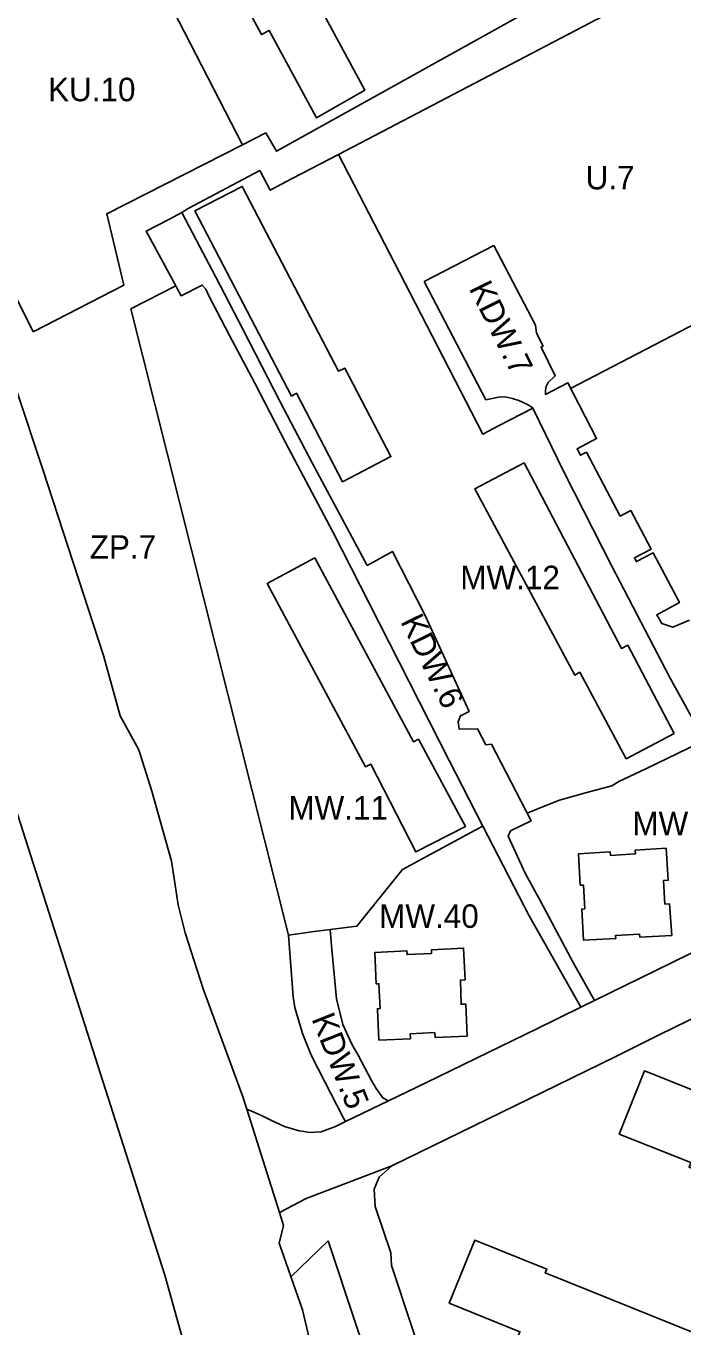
# Model space of a CAD drawing. Extents: x 7426178 to 7427732, y 5548847 to 5550287.
# Drawn here: x 7426935.7 to 7427061.4, y 5549279.8 to 5549528.9 of the extents above; entities that cross this region are included whole.
import ezdxf

# ---------------------------------------------------------------- set-up
doc = ezdxf.new("R2010")
doc.units = 0
for name, color, linetype in [('linie_rozgraniczajace', 7, 'Continuous'), ('linie_zabudowy_obowiazujace', 7, 'Continuous'), ('oznaczenia_przeznaczen', 7, 'Continuous')]:
    doc.layers.add(name, color=color, linetype=linetype)

msp = doc.modelspace()

# ---------------------------------------------------------------- linework, layer by layer
at = {"layer": 'linie_rozgraniczajace'}
for p, q in [((7427047.66, 5549531.65), (7426995.47, 5549504.35)), ((7427031.53, 5549378.2), (7427034.04, 5549379.24)), ((7427005.03, 5549323.13), (7426996.79, 5549319.15)), ((7426984.16, 5549301.77), (7426977.93, 5549321.54)), ((7426989.3, 5549304.41), (7427005.69, 5549310.69)), ((7426993.48, 5549296.31), (7426986.36, 5549289.44))]:
    msp.add_line(p, q, dxfattribs=at)
for points in [[(7426806.41, 5549611.72), (7426845.02, 5549569.73), (7426883.5, 5549515.53), (7426907.93, 5549461.17), (7426932.17, 5549384.03), (7426948.93, 5549331.51), (7426962.26, 5549289.73), (7427024.27, 5549067.18), (7427061.13, 5549001.37), (7427073.43, 5548973.27), (7427176.69, 5548896.63), (7427213.08, 5548849.03)], [(7426981.55, 5549508.5), (7426983.59, 5549504.94), (7427038.6, 5549535.58), (7427012.99, 5549581.89), (7427004.97, 5549596.59)], [(7426946.41, 5549565.6), (7426951.05, 5549557.05), (7426954.75, 5549559.04), (7426966.21, 5549536.1), (7426962.71, 5549534.23), (7426977.08, 5549506.2)], [(7426904.88, 5549532.73), (7426911.01, 5549522.31), (7426916.04, 5549512.37), (7426937.03, 5549470.34)], [(7426937.03, 5549470.34), (7426954.41, 5549479.33), (7426951.13, 5549492.97), (7426977.08, 5549506.2), (7426981.55, 5549508.5)], [(7426995.47, 5549504.35), (7426986.57, 5549499.72)], [(7426995.47, 5549504.35), (7427009.1, 5549477.89), (7427023.06, 5549450.78), (7427026.1, 5549452.36)], [(7426986.57, 5549499.72), (7426982.37, 5549497.52), (7426980.42, 5549501.25), (7426966.72, 5549494), (7426965.49, 5549493.2), (7426963, 5549491.9), (7426958.69, 5549489.65), (7426963.14, 5549481.4), (7426964.33, 5549479.18), (7426964.53, 5549478.8), (7426965.35, 5549477.27), (7426969.4, 5549479.32), (7426970.08, 5549478.53), (7426970.7, 5549477.16), (7426974.58, 5549469.81), (7426979.44, 5549460.54), (7426985.35, 5549449.18), (7426987.6, 5549444.84)], [(7427044.41, 5549342.33), (7427040.38, 5549349.62), (7427034.08, 5549361.35), (7427031.17, 5549366.71), (7427027.92, 5549373.83), (7427028.39, 5549374.82), (7427032.3, 5549376.73), (7427024.73, 5549391.45), (7427023.66, 5549391.29), (7427022.08, 5549394.33), (7427018.55, 5549394.28), (7427018.37, 5549395.71), (7427018.82, 5549396.86), (7427020.44, 5549397.69), (7427012.06, 5549416.04), (7427005.81, 5549428.29), (7427000.95, 5549425.64), (7426990.45, 5549445.27), (7426984.33, 5549456.95), (7426977.22, 5549470.73), (7426973.57, 5549477.8), (7426971.21, 5549482.33), (7426968.95, 5549486.67), (7426965.49, 5549493.2)], [(7427011.84, 5549479.99), (7427025.18, 5549486.88), (7427033.14, 5549471.62), (7427033.35, 5549470.12), (7427034.61, 5549467.65), (7427034.22, 5549467.44), (7427036.92, 5549461.93), (7427035.56, 5549460.65), (7427035.2, 5549459.92), (7427035.07, 5549459.19), (7427035.05, 5549458.39), (7427039.34, 5549460.58), (7427044.85, 5549449.93), (7427041.11, 5549447.97), (7427041.75, 5549446.73), (7427042.9, 5549447.33), (7427049.37, 5549435.08), (7427051.39, 5549436.13), (7427055.26, 5549428.78), (7427052.07, 5549427.1), (7427052.45, 5549426.38), (7427055.64, 5549428.06), (7427060.67, 5549418.52), (7427056.36, 5549416.2), (7427057.35, 5549414.52), (7427059.42, 5549413.84), (7427062.59, 5549415.17)], [(7427023.67, 5549457.37), (7427011.84, 5549479.99)], [(7427039.88, 5549459.54), (7427076.89, 5549478.82), (7427089.3, 5549481.03)], [(7426985.93, 5549354.84), (7426955.73, 5549474.75), (7426964.33, 5549479.18)], [(7426992.18, 5549317.21), (7426991, 5549317.16), (7426989.83, 5549317.1), (7426988.88, 5549317.26), (7426987.93, 5549317.42), (7426985.16, 5549318.25), (7426982.53, 5549319.42), (7426980.83, 5549320.24), (7426979.12, 5549321.06), (7426977.93, 5549321.54), (7426977.13, 5549324.09), (7426969.55, 5549344.6), (7426966.16, 5549355.3), (7426964.77, 5549360.68), (7426963.54, 5549369.01), (7426959.75, 5549382.4), (7426957.29, 5549390.35), (7426953.68, 5549396.84), (7426950.49, 5549408.37), (7426938.9, 5549444.02), (7426933.99, 5549458.8), (7426931, 5549467.22)], [(7427032.67, 5549455.78), (7427032.66, 5549455.8), (7427031.52, 5549456.5), (7427029.95, 5549457.2), (7427028.73, 5549457.6), (7427027.58, 5549457.84), (7427026.39, 5549457.91), (7427023.67, 5549457.37)], [(7427081.6, 5549360.57), (7427078.79, 5549367.94), (7427072.68, 5549379.11), (7427058.93, 5549404.03), (7427047.75, 5549425.49), (7427038.72, 5549443.34), (7427032.67, 5549455.78), (7427026.1, 5549452.36)], [(7426987.6, 5549444.84), (7426994.35, 5549432.07), (7427001.32, 5549418.4), (7427016.61, 5549388.28), (7427023.09, 5549375.73), (7427031.95, 5549358.56), (7427041.76, 5549341.19), (7427041.83, 5549341.06)], [(7427034.04, 5549379.24), (7427037.74, 5549380.71), (7427042.75, 5549382.08), (7427047.76, 5549383.46), (7427049.11, 5549384.26), (7427054.36, 5549386.77), (7427064.27, 5549391.56), (7427065.49, 5549392.15)], [(7426993.85, 5549355.91), (7426998.99, 5549356.56), (7427007.72, 5549367.45), (7427021.6, 5549374.93), (7427023.09, 5549375.73)], [(7427041.83, 5549341.06), (7427059.03, 5549349.51), (7427078.08, 5549358.85), (7427087.23, 5549363.32)], [(7427041.83, 5549341.06), (7427033.52, 5549336.98), (7427012.27, 5549326.62), (7427005.03, 5549323.13), (7427003.92, 5549323.68), (7427002.7, 5549325.49), (7427001.75, 5549327.03), (7426999.23, 5549331.88), (7426998.09, 5549333.84), (7426996.32, 5549337.76), (7426995.08, 5549342.65), (7426994.19, 5549352.1), (7426993.85, 5549355.91), (7426990.84, 5549355.53), (7426985.93, 5549354.84), (7426986.81, 5549343.04), (7426987.1, 5549340.99), (7426988.57, 5549336.04), (7426990.28, 5549331.72), (7426992.87, 5549326.78), (7426996.32, 5549320.06), (7426996.79, 5549319.15)], [(7427013.13, 5549268.92), (7427005.61, 5549291.59), (7427005.47, 5549294.05), (7427002.49, 5549302.88), (7427002.29, 5549306.24), (7427003.23, 5549308.53), (7427005.69, 5549310.69), (7427031.81, 5549323.48), (7427048.39, 5549331.54), (7427056.79, 5549335.77), (7427084.49, 5549349.29), (7427088.69, 5549351.18), (7427088.82, 5549351.24)], [(7426992.18, 5549317.21), (7426994.87, 5549318.23), (7426996.79, 5549319.15)], [(7427027.29, 5549140.82), (7427024.38, 5549151.16), (7427019.99, 5549166.88), (7427014.09, 5549187.33), (7427012.41, 5549194.63), (7427003.06, 5549226.37), (7426993.93, 5549257.37), (7426990.69, 5549268.36), (7426989.92, 5549277.44), (7426988.58, 5549283.13), (7426984.1, 5549295.88), (7426984.96, 5549299.25), (7426984.16, 5549301.77), (7426989.3, 5549304.41)], [(7426994.7, 5549292.67), (7426993.48, 5549296.31)], [(7427005.14, 5549261.35), (7426997.53, 5549284.23), (7426994.7, 5549292.67)]]:
    msp.add_lwpolyline(points, dxfattribs=at)
at = {"layer": 'linie_zabudowy_obowiazujace'}
for points in [[(7426961.83, 5549562.39), (7426980.72, 5549527.28), (7426982.23, 5549528.09), (7426991.25, 5549511.32), (7427000.49, 5549516.61), (7426991.33, 5549533.62), (7426989.83, 5549532.81), (7426971.07, 5549567.67), (7426970.1, 5549567.12)], [(7426986.45, 5549458.08), (7426987.45, 5549458.6), (7426996.26, 5549441.67), (7427005.48, 5549446.47), (7426996.66, 5549463.43), (7426995.47, 5549462.81), (7426977.05, 5549498.22), (7426968.01, 5549493.51), (7426986.45, 5549458.08)], [(7427059.68, 5549393.45), (7427050.79, 5549410.38), (7427049.6, 5549409.75), (7427030.96, 5549445.26), (7427021.54, 5549440.29), (7427040.66, 5549404.65), (7427041.63, 5549405.18), (7427050.51, 5549388.64), (7427059.68, 5549393.45)], [(7427010.77, 5549392.35), (7427009.82, 5549391.84), (7426990.92, 5549427.07), (7426981.79, 5549422.17), (7427000.61, 5549387.1), (7427001.63, 5549387.62), (7427010.29, 5549370.8), (7427019.73, 5549375.66), (7427010.77, 5549392.35)], [(7427041.73, 5549364.41), (7427042.33, 5549364.44), (7427042.58, 5549359.9), (7427042, 5549359.86), (7427042.32, 5549353.9), (7427048.5, 5549354.23), (7427048.47, 5549354.81), (7427053.06, 5549355.06), (7427053.09, 5549354.49), (7427059.21, 5549354.82), (7427058.82, 5549360.85), (7427057.9, 5549360.79), (7427057.61, 5549365.32), (7427058.53, 5549365.38), (7427058.14, 5549371.53), (7427052.24, 5549371.14), (7427052.29, 5549370.44), (7427047.47, 5549370.13), (7427047.42, 5549370.83), (7427041.41, 5549370.45), (7427041.73, 5549364.41)], [(7427003.18, 5549334.73), (7427009.23, 5549335.01), (7427009.19, 5549335.95), (7427013.89, 5549336.21), (7427013.94, 5549335.28), (7427020.06, 5549335.53), (7427019.84, 5549341.67), (7427018.93, 5549341.64), (7427018.79, 5549346.24), (7427019.68, 5549346.28), (7427019.39, 5549352.39), (7427013.25, 5549352.06), (7427013.28, 5549351.36), (7427008.6, 5549351.13), (7427008.56, 5549351.83), (7427002.41, 5549351.52), (7427002.68, 5549345.53), (7427003.19, 5549345.55), (7427003.29, 5549343.1), (7427003.41, 5549340.79), (7427002.91, 5549340.77), (7427002.92, 5549340.61), (7427003.18, 5549334.73)], [(7427067.51, 5549322.41), (7427067.88, 5549323.34), (7427053.99, 5549328.86), (7427049.18, 5549316.78), (7427062.89, 5549311.33), (7427062.52, 5549310.41), (7427116.42, 5549288.99), (7427121.22, 5549301.07), (7427067.51, 5549322.41)], [(7427088.96, 5549268.43), (7427035.01, 5549290.19), (7427035.3, 5549290.91), (7427021.52, 5549296.47), (7427016.64, 5549284.38), (7427030.18, 5549278.92), (7427029.78, 5549277.94), (7427083.97, 5549256.08), (7427088.96, 5549268.43)]]:
    msp.add_lwpolyline(points, dxfattribs=at)

# ---------------------------------------------------------------- texts
at = {"layer": 'oznaczenia_przeznaczen'}
for s, p in [('KU.10', (7426939.9, 5549514.52)), ('U.7', (7427042.74, 5549497.65)), ('ZP.7', (7426947.87, 5549426.92)), ('MW.12', (7427018.76, 5549421.09)), ('MW.11', (7426985.88, 5549376.99)), ('MW.41', (7427051.68, 5549374)), ('MW.40', (7427003.24, 5549356.25))]:
    msp.add_text(s, height=4.5, dxfattribs=at).set_placement(p)
for s, rotation, p in [('KDW.7', 296.4166, (7427020.34, 5549478.69)), ('KDW.6', 296.1625, (7427007.23, 5549414.93)), ('KDW.5', 291.6596, (7426990.24, 5549338.86))]:
    msp.add_text(s, height=4.5, rotation=rotation, dxfattribs=at).set_placement(p)

doc.saveas('drawing.dxf')
